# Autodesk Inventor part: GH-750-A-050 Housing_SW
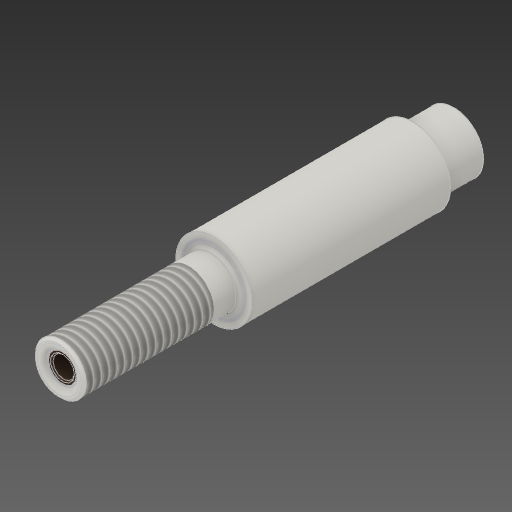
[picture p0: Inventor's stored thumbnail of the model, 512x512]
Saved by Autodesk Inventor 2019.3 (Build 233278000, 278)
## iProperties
Created: 2018-11
Part Number: GH-750-A-050 Housing_SW
Material: Generic
Document SubType Name: Modeling
Designer: Justin
Density: 1 g/cm^3
Appearance: Default
Author: Justin
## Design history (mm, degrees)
node "Assembly1"
body "Solid1"
node "Part1:1"
node "Part2:1"
body "Solid2"
node "Part3:1"
body "Solid3"
node "Part4:1"
body "Solid4"
node "Part5:1"
body "Solid5"
